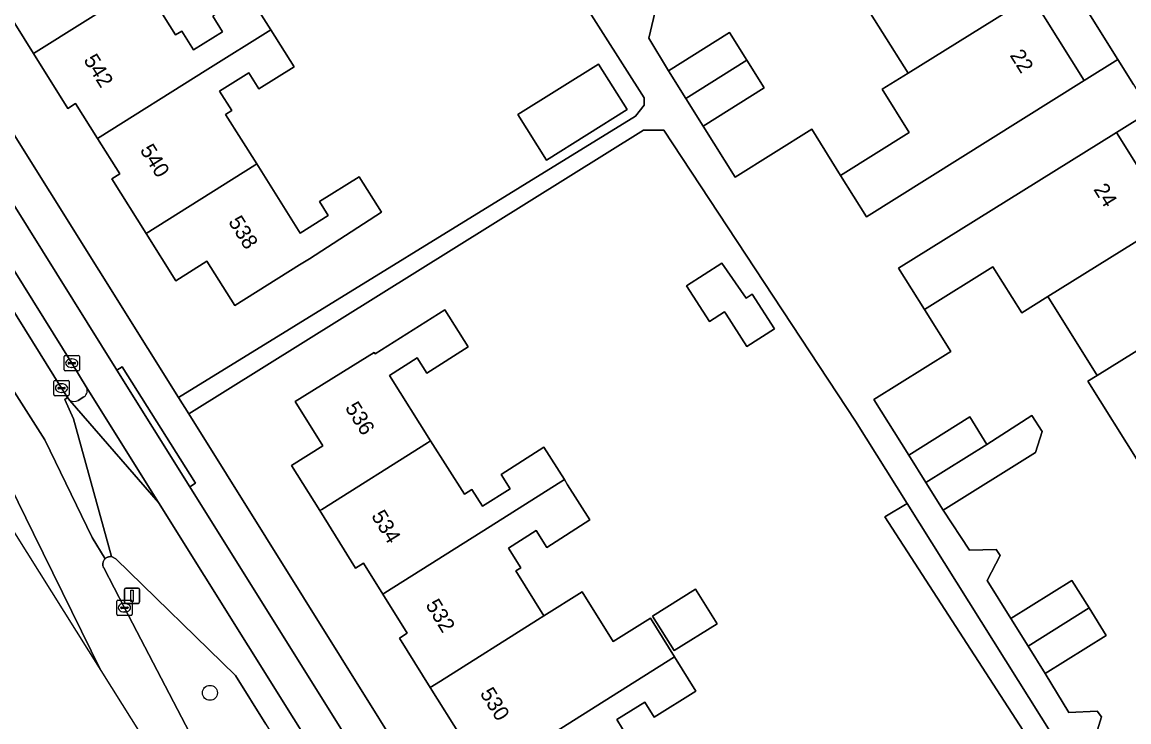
# Model space of a CAD drawing. Extents: x 159664 to 160323, y 385312 to 386115.
# Drawn here: x 159717.3 to 159789.6, y 385791.8 to 385837.6 of the extents above; entities that cross this region are included whole.
import ezdxf

# ---------------------------------------------------------------- set-up
doc = ezdxf.new("R2010")
doc.units = 0
for name, color, linetype in [('IMGEO_Berm_groen', 7, 'Continuous'), ('IMGEO_Berm_open', 7, 'Continuous'), ('IMGEO_Boom', 7, 'Continuous'), ('IMGEO_Erf', 7, 'Continuous'), ('IMGEO_Fietspad_gesloten', 7, 'Continuous'), ('IMGEO_Kolk', 7, 'Continuous'), ('IMGEO_Lichtmast', 7, 'Continuous'), ('IMGEO_Pand', 7, 'Continuous'), ('IMGEO_Pand_nummerreeks', 7, 'Continuous'), ('IMGEO_Rijbaan_lokaal_open', 7, 'Continuous'), ('IMGEO_Rijbaan_regionaal_gesloten', 7, 'Continuous'), ('IMGEO_Verkeerseiland_open', 7, 'Continuous'), ('IMGEO_Voetpad_open', 7, 'Continuous')]:
    doc.layers.add(name, color=color, linetype=linetype)

msp = doc.modelspace()

# ---------------------------------------------------------------- linework, layer by layer
at = {"layer": 'IMGEO_Berm_groen'}
msp.add_lwpolyline([(159733.256, 385791.672), (159731.268, 385794.861), (159723.446, 385802.492), (159723.154, 385802.631), (159723.109, 385802.634), (159723.064, 385802.633), (159723.019, 385802.628), (159722.975, 385802.619), (159722.932, 385802.607), (159722.891, 385802.59), (159722.85, 385802.57), (159722.812, 385802.546), (159722.776, 385802.519), (159722.743, 385802.489), (159722.712, 385802.456), (159722.685, 385802.42), (159722.661, 385802.382), (159722.64, 385802.342), (159722.623, 385802.301), (159722.61, 385802.258), (159722.601, 385802.214), (159722.595, 385802.169), (159722.594, 385802.124), (159722.596, 385802.079), (159722.603, 385802.035), (159722.614, 385801.991), (159722.628, 385801.949), (159722.646, 385801.907), (159722.655, 385801.891), (159724.007, 385799.293), (159732.539, 385782.948)], dxfattribs=at)
at = {"layer": 'IMGEO_Berm_open'}
for points in [[(159685.962, 385868.059), (159687.762, 385865.202), (159698.166, 385848.523), (159707.398, 385833.746), (159719.9, 385813.65), (159720.286, 385813.027), (159720.44, 385812.85)], [(159721.514, 385813.73), (159720.566, 385815.282), (159708.631, 385834.436), (159699.356, 385849.333)], [(159720.974, 385812.847), (159721.354, 385813.072)]]:
    msp.add_lwpolyline(points, dxfattribs=at)
for centre, radius, start, end in [((159721.093, 385813.484), 0.487, 302.33394, 30.33234), ((159720.709, 385813.245), 0.478, 235.73011, 303.62613)]:
    msp.add_arc(centre, radius, start, end, dxfattribs=at)
at = {"layer": 'IMGEO_Boom'}
msp.add_circle((159729.595, 385793.73), 0.489, dxfattribs=at)
at = {"layer": 'IMGEO_Erf'}
for points in [[(159783.276, 385839.278), (159786.733, 385833.76), (159788.93, 385835.134), (159751.956, 385894.264)], [(159725.268, 385840.05), (159727.349, 385836.736), (159727.751, 385836.987), (159728.525, 385835.755), (159730.423, 385836.946), (159729.78, 385837.969)], [(159732.097, 385839.423), (159733.573, 385837.072), (159735.091, 385834.653), (159732.786, 385833.206), (159732.126, 385834.258), (159730.218, 385833.06), (159731.015, 385831.789), (159730.621, 385831.542), (159732.653, 385828.305), (159735.492, 385823.783), (159737.318, 385824.93), (159736.747, 385825.839), (159739.344, 385827.469), (159740.804, 385825.144), (159736.096, 385822.103), (159735.453, 385821.701), (159731.213, 385819.05), (159729.401, 385821.949), (159727.359, 385820.673), (159725.422, 385823.767), (159723.188, 385827.336), (159723.697, 385827.654), (159722.25, 385829.965), (159720.818, 385832.253), (159720.309, 385831.935), (159718.061, 385835.526), (159716.118, 385838.631)], [(159758.773, 385838.63), (159758.279, 385836.531), (159759.569, 385834.393), (159763.553, 385836.886), (159764.684, 385835.078), (159765.816, 385833.27), (159761.832, 385830.777), (159763.92, 385827.44), (159768.92, 385830.568), (159770.808, 385827.55), (159775.293, 385830.356), (159773.526, 385833.182), (159775.221, 385834.242), (159771.881, 385839.579)], [(159791.049, 385831.741), (159788.849, 385830.368), (159792.419, 385824.644)], [(159790.298, 385808.779), (159786.975, 385814.104), (159787.57, 385814.477), (159784.343, 385819.629), (159782.647, 385818.568), (159780.758, 385821.586), (159776.283, 385818.784), (159778.004, 385816.035), (159772.991, 385812.903), (159775.26, 385809.272), (159779.246, 385811.762), (159780.372, 385809.96), (159783.313, 385811.855), (159783.99, 385810.805), (159783.539, 385809.433), (159777.512, 385805.668), (159779.229, 385803.051), (159780.975, 385803.096), (159781.246, 385802.718), (159780.378, 385801.07), (159781.934, 385798.585), (159785.917, 385801.08), (159787.044, 385799.281), (159788.171, 385797.481), (159784.188, 385794.986), (159785.732, 385792.454), (159787.572, 385792.541), (159787.852, 385792.159), (159787.239, 385790.114)], [(159746.012, 385790.854), (159743.996, 385794.079), (159741.978, 385797.309), (159742.487, 385797.628), (159740.892, 385800.18), (159739.625, 385802.208), (159739.116, 385801.889), (159736.772, 385805.64), (159734.93, 385808.589), (159736.982, 385809.871), (159735.174, 385812.764), (159739.415, 385815.414), (159740.333, 385815.987), (159740.399, 385815.883), (159744.948, 385818.761), (159746.479, 385816.339), (159743.771, 385814.626), (159743.141, 385815.622), (159741.32, 385814.47), (159744.016, 385810.208), (159746.224, 385806.717), (159746.719, 385807.03), (159747.417, 385805.928), (159749.213, 385807.064), (159748.617, 385808.006), (159751.424, 385809.782), (159752.763, 385807.665), (159752.973, 385807.333), (159754.43, 385805.029), (159751.603, 385803.24), (159750.908, 385804.338), (159749.1, 385803.195), (159749.913, 385801.91), (159749.581, 385801.7), (159751.412, 385798.755), (159753.919, 385800.336), (159755.95, 385797.087), (159758.386, 385798.601), (159759.952, 385796.081), (159761.352, 385793.828), (159758.637, 385792.14), (159758.025, 385793.125), (159756.179, 385791.978), (159756.929, 385790.771)]]:
    msp.add_lwpolyline(points, dxfattribs=at)
for points in [[(159749.78, 385845.505), (159747.52, 385845.517), (159747.246, 385845.967), (159748.353, 385847.97), (159740.221, 385860.856), (159709.605, 385841.691), (159725.533, 385816.246), (159727.547, 385813.028), (159757.404, 385831.429), (159757.978, 385832.141), (159757.978, 385832.633)], [(159749.726, 385831.528), (159754.992, 385834.824), (159756.851, 385831.852), (159751.585, 385828.557)], [(159775.161, 385806.096), (159771.78, 385811.483), (159759.25, 385830.512), (159757.926, 385830.512), (159728.212, 385811.963), (159753.159, 385772), (159771.727, 385783.591), (159776.451, 385786.658), (159782.979, 385790.896), (159773.707, 385805.242)], [(159760.745, 385820.332), (159763.053, 385821.817), (159764.632, 385819.537), (159765.029, 385819.793), (159766.49, 385817.524), (159764.693, 385816.367), (159763.336, 385818.476), (159763.233, 385818.637), (159762.245, 385818.001)], [(159758.528, 385798.751), (159761.338, 385800.498), (159762.738, 385798.245), (159759.928, 385796.498)]]:
    msp.add_lwpolyline(points, close=True, dxfattribs=at)
at = {"layer": 'IMGEO_Fietspad_gesloten'}
msp.add_lwpolyline([(159689.016, 385865.92), (159699.356, 385849.333), (159708.631, 385834.436), (159720.566, 385815.282), (159721.514, 385813.73), (159726.241, 385806.163), (159746.799, 385773.289), (159761.349, 385750), (159769.568, 385736.844), (159790.48, 385703.378), (159792.384, 385704.563), (159772.652, 385736.21), (159767.476, 385744.488), (159764.031, 385750), (159753.712, 385766.513), (159748.937, 385774.15), (159728.287, 385807.194), (159723.506, 385814.826), (159723.438, 385814.935), (159698.624, 385854.738), (159688.899, 385870.747), (159686.756, 385869.506), (159687.159, 385868.865)], close=True, dxfattribs=at)
at = {"layer": 'IMGEO_Kolk'}
for p, q in [((159720.065, 385814.854), (159720.065, 385815.706)), ((159720.14, 385815.78), (159720.992, 385815.78)), ((159720.324, 385815.274), (159720.324, 385815.286)), ((159720.762, 385815.237), (159720.364, 385815.237)), ((159720.367, 385815.323), (159720.765, 385815.323)), ((159720.553, 385815.56), (159720.578, 385815.56)), ((159720.808, 385815.286), (159720.808, 385815.274)), ((159721.066, 385815.706), (159721.066, 385814.854)), ((159720.992, 385814.78), (159720.14, 385814.78)), ((159720.576, 385815), (159720.551, 385815)), ((159719.398, 385813.223), (159719.398, 385814.075)), ((159719.473, 385814.149), (159720.325, 385814.149)), ((159719.886, 385813.929), (159719.911, 385813.929)), ((159720.399, 385814.075), (159720.399, 385813.223)), ((159720.325, 385813.149), (159719.473, 385813.149)), ((159719.657, 385813.643), (159719.657, 385813.655)), ((159720.095, 385813.606), (159719.697, 385813.606)), ((159719.7, 385813.692), (159720.098, 385813.692)), ((159719.909, 385813.369), (159719.884, 385813.369)), ((159720.141, 385813.655), (159720.141, 385813.643)), ((159723.507, 385798.868), (159723.507, 385799.72)), ((159723.582, 385799.794), (159724.434, 385799.794)), ((159723.766, 385799.288), (159723.766, 385799.3)), ((159723.809, 385799.337), (159724.207, 385799.337)), ((159723.995, 385799.574), (159724.02, 385799.574)), ((159724.25, 385799.3), (159724.25, 385799.288)), ((159724.508, 385799.72), (159724.508, 385798.868)), ((159724.434, 385798.794), (159723.582, 385798.794)), ((159724.204, 385799.251), (159723.806, 385799.251)), ((159724.018, 385799.014), (159723.993, 385799.014))]:
    msp.add_line(p, q, dxfattribs=at)
for points in [[(159720.065, 385814.854), (159720.065, 385815.706)], [(159720.14, 385815.78), (159720.992, 385815.78)], [(159721.066, 385815.706), (159721.066, 385814.854)], [(159720.992, 385814.78), (159720.14, 385814.78)], [(159719.398, 385813.223), (159719.398, 385814.075)], [(159719.473, 385814.149), (159720.325, 385814.149)], [(159720.399, 385814.075), (159720.399, 385813.223)], [(159720.325, 385813.149), (159719.473, 385813.149)], [(159723.507, 385798.868), (159723.507, 385799.72)], [(159723.582, 385799.794), (159724.434, 385799.794)], [(159724.508, 385799.72), (159724.508, 385798.868)], [(159724.434, 385798.794), (159723.582, 385798.794)]]:
    msp.add_lwpolyline(points, dxfattribs=at)
for centre, radius, start, end in [((159720.142, 385815.704), 0.0765, 91.55205, 178.44795), ((159720.142, 385815.704), 0.0765, 91.55205, 178.44795), ((159720.364, 385815.283), 0.0403, 85.87752, 175.75265), ((159720.361, 385815.273), 0.0366, 178.93798, 274.71019), ((159720.765, 385815.28), 0.043, 264.86636, 352.45326), ((159720.769, 385815.285), 0.0386, 1.73085, 96.63898), ((159720.99, 385815.704), 0.0765, 1.55205, 88.44795), ((159720.99, 385815.704), 0.0765, 1.55205, 88.44795), ((159720.142, 385814.856), 0.0765, 181.55205, 268.44795), ((159720.142, 385814.856), 0.0765, 181.55205, 268.44795), ((159720.99, 385814.856), 0.0765, 271.55205, 358.44795), ((159720.99, 385814.856), 0.0765, 271.55205, 358.44795), ((159719.475, 385814.073), 0.0765, 91.55205, 178.44795), ((159719.475, 385814.073), 0.0765, 91.55205, 178.44795), ((159720.323, 385814.073), 0.0765, 1.55205, 88.44795), ((159720.323, 385814.073), 0.0765, 1.55205, 88.44795), ((159719.475, 385813.225), 0.0765, 181.55205, 268.44795), ((159719.475, 385813.225), 0.0765, 181.55205, 268.44795), ((159719.697, 385813.652), 0.0403, 85.87752, 175.75265), ((159719.694, 385813.642), 0.0366, 178.93798, 274.71019), ((159720.098, 385813.649), 0.043, 264.86636, 352.45326), ((159720.102, 385813.654), 0.0386, 1.73085, 96.63898), ((159720.323, 385813.225), 0.0765, 271.55205, 358.44795), ((159720.323, 385813.225), 0.0765, 271.55205, 358.44795), ((159723.584, 385799.718), 0.0765, 91.55205, 178.44795), ((159723.584, 385799.718), 0.0765, 91.55205, 178.44795), ((159723.806, 385799.297), 0.0403, 85.87752, 175.75265), ((159723.803, 385799.287), 0.0366, 178.93798, 274.71019), ((159724.207, 385799.294), 0.043, 264.86636, 352.45326), ((159724.211, 385799.299), 0.0386, 1.73085, 96.63898), ((159724.432, 385799.718), 0.0765, 1.55205, 88.44795), ((159724.432, 385799.718), 0.0765, 1.55205, 88.44795), ((159723.584, 385798.87), 0.0765, 181.55205, 268.44795), ((159723.584, 385798.87), 0.0765, 181.55205, 268.44795), ((159724.432, 385798.87), 0.0765, 271.55205, 358.44795), ((159724.432, 385798.87), 0.0765, 271.55205, 358.44795)]:
    msp.add_arc(centre, radius, start, end, dxfattribs=at)
for centre, major_axis, ratio, start_param, end_param in [((159720.552, 385815.28), (-0.387, 0.002), 0.722429, 4.712389, 7.853982), ((159720.577, 385815.28), (-0.39, 0.002), 0.717154, 1.570796, 4.712389), ((159719.885, 385813.649), (-0.387, 0.002), 0.722429, 4.712389, 7.853982), ((159719.91, 385813.649), (-0.39, 0.002), 0.717154, 1.570796, 4.712389), ((159723.994, 385799.294), (-0.387, 0.002), 0.722429, 4.712389, 7.853982), ((159724.019, 385799.294), (-0.39, 0.002), 0.717154, 1.570796, 4.712389)]:
    msp.add_ellipse(centre, major_axis=major_axis, ratio=ratio, start_param=start_param, end_param=end_param, dxfattribs=at)
at = {"layer": 'IMGEO_Lichtmast'}
for p, q in [((159724.005, 385799.674), (159724.005, 385800.474)), ((159724.005, 385800.474), (159724.005, 385799.674)), ((159724.105, 385800.574), (159724.895, 385800.574)), ((159724.895, 385800.574), (159724.105, 385800.574)), ((159724.995, 385800.474), (159724.995, 385799.674)), ((159724.995, 385799.674), (159724.995, 385800.474)), ((159724.895, 385799.574), (159724.105, 385799.574)), ((159724.105, 385799.574), (159724.895, 385799.574))]:
    msp.add_line(p, q, dxfattribs=at)
msp.add_lwpolyline([(159724.425, 385800.449), (159724.575, 385800.449), (159724.575, 385799.699), (159724.425, 385799.699), (159724.425, 385800.449)], dxfattribs=at)
for centre, start, end in [((159724.105, 385800.474), 90, 180), ((159724.105, 385800.474), 90, 180), ((159724.895, 385800.474), 0, 90), ((159724.895, 385800.474), 360, 90), ((159724.105, 385799.674), 180, 270), ((159724.105, 385799.674), 180, 270), ((159724.895, 385799.674), 270, 0), ((159724.895, 385799.674), 270, 0)]:
    msp.add_arc(centre, 0.1, start, end, dxfattribs=at)
at = {"layer": 'IMGEO_Pand'}
for points in [[(159716.363, 385842.815), (159718.175, 385839.916), (159716.118, 385838.631), (159718.061, 385835.526), (159725.165, 385839.985), (159725.268, 385840.05), (159722.462, 385844.52), (159724.34, 385845.699), (159724.924, 385844.769), (159724.715, 385844.637), (159725.712, 385843.049), (159728.503, 385844.802), (159726.034, 385848.734), (159721.394, 385845.894)], [(159780.04, 385844.443), (159779.933, 385844.614), (159771.881, 385839.579), (159775.221, 385834.242), (159783.276, 385839.278)], [(159725.165, 385839.985), (159718.061, 385835.526), (159720.309, 385831.935), (159720.818, 385832.253), (159722.25, 385829.965), (159729.463, 385834.492), (159733.573, 385837.072), (159732.097, 385839.423), (159729.78, 385837.969), (159730.423, 385836.946), (159728.525, 385835.755), (159727.751, 385836.987), (159727.349, 385836.736), (159725.268, 385840.05)], [(159786.733, 385833.76), (159783.276, 385839.278), (159775.221, 385834.242), (159773.526, 385833.182), (159775.293, 385830.356), (159770.808, 385827.55), (159772.494, 385824.856)], [(159729.463, 385834.492), (159722.25, 385829.965), (159723.697, 385827.654), (159723.188, 385827.336), (159725.422, 385823.767), (159732.519, 385828.221), (159732.653, 385828.305), (159730.621, 385831.542), (159731.015, 385831.789), (159730.218, 385833.06), (159732.126, 385834.258), (159732.786, 385833.206), (159735.091, 385834.653), (159733.573, 385837.072)], [(159763.553, 385836.886), (159759.569, 385834.393), (159760.7, 385832.585), (159764.684, 385835.078)], [(159749.726, 385831.528), (159751.585, 385828.557), (159756.851, 385831.852), (159754.992, 385834.824)], [(159765.816, 385833.27), (159764.684, 385835.078), (159760.7, 385832.585), (159761.832, 385830.777)], [(159784.343, 385819.629), (159792.419, 385824.644), (159788.849, 385830.368), (159774.595, 385821.481), (159776.283, 385818.784), (159780.758, 385821.586), (159782.647, 385818.568)], [(159732.519, 385828.221), (159725.422, 385823.767), (159727.359, 385820.673), (159729.401, 385821.949), (159731.213, 385819.05), (159735.453, 385821.701), (159736.096, 385822.103), (159740.804, 385825.144), (159739.344, 385827.469), (159736.747, 385825.839), (159737.318, 385824.93), (159735.492, 385823.783), (159732.653, 385828.305)], [(159795.515, 385819.679), (159792.419, 385824.644), (159784.343, 385819.629), (159787.57, 385814.477), (159795.636, 385819.485)], [(159763.053, 385821.817), (159760.745, 385820.332), (159762.245, 385818.001), (159763.233, 385818.637), (159763.336, 385818.476), (159764.693, 385816.367), (159766.49, 385817.524), (159765.029, 385819.793), (159764.632, 385819.537)], [(159796.231, 385819.855), (159796.109, 385820.05), (159795.515, 385819.679), (159795.636, 385819.485), (159787.57, 385814.477), (159786.975, 385814.104), (159790.298, 385808.779), (159798.37, 385813.791), (159798.487, 385813.604), (159799.675, 385814.346), (159799.56, 385814.53)], [(159744.016, 385810.208), (159741.32, 385814.47), (159743.141, 385815.622), (159743.771, 385814.626), (159746.479, 385816.339), (159744.948, 385818.761), (159740.399, 385815.883), (159740.333, 385815.987), (159739.415, 385815.414), (159735.174, 385812.764), (159736.982, 385809.871), (159734.93, 385808.589), (159736.772, 385805.64), (159736.902, 385805.722), (159743.802, 385810.073)], [(159779.246, 385811.762), (159775.26, 385809.272), (159776.386, 385807.47), (159780.372, 385809.96)], [(159783.313, 385811.855), (159780.372, 385809.96), (159776.386, 385807.47), (159777.512, 385805.668), (159783.539, 385809.433), (159783.99, 385810.805)], [(159746.719, 385807.03), (159746.224, 385806.717), (159744.016, 385810.208), (159743.802, 385810.073), (159736.902, 385805.722), (159736.772, 385805.64), (159739.116, 385801.889), (159739.625, 385802.208), (159740.892, 385800.18), (159741.018, 385800.259), (159747.909, 385804.605), (159752.763, 385807.665), (159751.424, 385809.782), (159748.617, 385808.006), (159749.213, 385807.064), (159747.417, 385805.928)], [(159749.1, 385803.195), (159750.908, 385804.338), (159751.603, 385803.24), (159754.43, 385805.029), (159752.973, 385807.333), (159752.763, 385807.665), (159747.909, 385804.605), (159741.018, 385800.259), (159740.892, 385800.18), (159742.487, 385797.628), (159741.978, 385797.309), (159743.996, 385794.079), (159744.653, 385794.493), (159750.997, 385798.493), (159751.412, 385798.755), (159749.581, 385801.7), (159749.913, 385801.91)], [(159787.044, 385799.281), (159785.917, 385801.08), (159781.934, 385798.585), (159783.061, 385796.785)], [(159759.952, 385796.081), (159758.386, 385798.601), (159755.95, 385797.087), (159753.919, 385800.336), (159751.412, 385798.755), (159750.997, 385798.493), (159744.653, 385794.493), (159743.996, 385794.079), (159746.012, 385790.854), (159746.522, 385791.172), (159748.117, 385788.619), (159748.289, 385788.727), (159755.36, 385793.186)], [(159758.528, 385798.751), (159759.928, 385796.498), (159762.738, 385798.245), (159761.338, 385800.498)], [(159783.061, 385796.785), (159784.188, 385794.986), (159788.171, 385797.481), (159787.044, 385799.281)], [(159758.584, 385787.162), (159756.505, 385790.508), (159756.929, 385790.771), (159756.179, 385791.978), (159758.025, 385793.125), (159758.637, 385792.14), (159761.352, 385793.828), (159759.952, 385796.081), (159755.36, 385793.186), (159748.289, 385788.727), (159748.117, 385788.619), (159749.399, 385786.567), (159748.89, 385786.249), (159751.221, 385782.519), (159751.393, 385782.627), (159758.36, 385787.02)]]:
    msp.add_lwpolyline(points, close=True, dxfattribs=at)
at = {"layer": 'IMGEO_Rijbaan_lokaal_open'}
msp.add_lwpolyline([(159720.286, 385813.027), (159720.121, 385812.906), (159720.687, 385811.648), (159723.154, 385802.631), (159723.446, 385802.492), (159731.268, 385794.861), (159733.256, 385791.672), (159735.48, 385788.106), (159745.908, 385771.421), (159759.303, 385750), (159767.282, 385737.246), (159778.388, 385719.445), (159788.935, 385702.551), (159789.008, 385702.435), (159790.48, 385703.378), (159769.568, 385736.844), (159761.349, 385750), (159746.799, 385773.289), (159726.241, 385806.163), (159720.44, 385812.85)], close=True, dxfattribs=at)
at = {"layer": 'IMGEO_Rijbaan_regionaal_gesloten'}
for points in [[(159707.398, 385833.746), (159698.166, 385848.523), (159687.762, 385865.202), (159685.962, 385868.059), (159683.457, 385865.842), (159689.98, 385855.614), (159704.448, 385832.81), (159718.81, 385810.264), (159721.888, 385803.885), (159722.743, 385802.489), (159722.776, 385802.519), (159722.812, 385802.546), (159722.85, 385802.57), (159722.891, 385802.59), (159722.932, 385802.607), (159722.975, 385802.619), (159723.019, 385802.628), (159723.064, 385802.633), (159723.109, 385802.634), (159723.154, 385802.631), (159720.687, 385811.648), (159720.121, 385812.906), (159720.286, 385813.027), (159719.9, 385813.65)], [(159722.474, 385795.185), (159718.071, 385804.138), (159716.049, 385808.25), (159711.375, 385815.569), (159700.472, 385832.883), (159681.056, 385863.717), (159680.046, 385862.823)]]:
    msp.add_lwpolyline(points, close=True, dxfattribs=at)
for points in [[(159681.056, 385863.717), (159700.472, 385832.883), (159711.375, 385815.569), (159716.049, 385808.25), (159718.071, 385804.138), (159722.474, 385795.185), (159793.146, 385682.519)], [(159732.539, 385782.948), (159724.007, 385799.293), (159722.655, 385801.891), (159722.646, 385801.907), (159722.628, 385801.949), (159722.614, 385801.991), (159722.603, 385802.035), (159722.596, 385802.079), (159722.594, 385802.124), (159722.595, 385802.169), (159722.601, 385802.214), (159722.61, 385802.258), (159722.623, 385802.301), (159722.64, 385802.342), (159722.661, 385802.382), (159722.685, 385802.42), (159722.712, 385802.456), (159722.743, 385802.489), (159721.888, 385803.885), (159718.81, 385810.264), (159704.448, 385832.81)]]:
    msp.add_lwpolyline(points, dxfattribs=at)
at = {"layer": 'IMGEO_Verkeerseiland_open'}
for points in [[(159720.44, 385812.85), (159726.241, 385806.163), (159721.514, 385813.73)], [(159721.354, 385813.072), (159720.974, 385812.847)]]:
    msp.add_lwpolyline(points, dxfattribs=at)
for centre, radius, start, end in [((159721.093, 385813.484), 0.487, 302.33394, 30.33234), ((159720.709, 385813.245), 0.478, 235.73011, 303.62613)]:
    msp.add_arc(centre, radius, start, end, dxfattribs=at)
at = {"layer": 'IMGEO_Voetpad_open'}
for points in [[(159741.032, 385918.933), (159740.787, 385919.315), (159737.177, 385917.789), (159749.768, 385897.575), (159749.851, 385897.63), (159751.956, 385894.264), (159788.93, 385835.134), (159789.958, 385833.49), (159791.049, 385831.741), (159827.962, 385772.584), (159830.13, 385769.11), (159843.706, 385747.354)], [(159698.624, 385854.738), (159723.438, 385814.935), (159723.506, 385814.826), (159723.865, 385815.051), (159728.647, 385807.43), (159728.287, 385807.194), (159748.937, 385774.15), (159749.31, 385774.375), (159754.077, 385766.751), (159753.712, 385766.513), (159764.031, 385750)], [(159749.78, 385845.505), (159757.978, 385832.633), (159757.978, 385832.141), (159757.404, 385831.429), (159727.547, 385813.028), (159728.212, 385811.963), (159757.926, 385830.512), (159759.25, 385830.512), (159771.78, 385811.483), (159775.161, 385806.096), (159790.372, 385781.858)], [(159728.212, 385811.963), (159727.547, 385813.028), (159725.533, 385816.246), (159709.605, 385841.691)], [(159789.958, 385833.49), (159788.93, 385835.134), (159786.733, 385833.76), (159772.494, 385824.856), (159770.808, 385827.55), (159768.92, 385830.568), (159763.92, 385827.44), (159761.832, 385830.777), (159760.7, 385832.585), (159759.569, 385834.393), (159758.279, 385836.531), (159758.773, 385838.63)], [(159789.739, 385786.105), (159788.616, 385787.906), (159787.239, 385790.114), (159787.852, 385792.159), (159787.572, 385792.541), (159785.732, 385792.454), (159784.188, 385794.986), (159783.061, 385796.785), (159781.934, 385798.585), (159780.378, 385801.07), (159781.246, 385802.718), (159780.975, 385803.096), (159779.229, 385803.051), (159777.512, 385805.668), (159776.386, 385807.47), (159775.26, 385809.272), (159772.991, 385812.903), (159778.004, 385816.035), (159776.283, 385818.784), (159774.595, 385821.481), (159788.849, 385830.368), (159791.049, 385831.741)], [(159766.915, 385750), (159753.983, 385770.681), (159753.16, 385771.998), (159753.159, 385772), (159728.212, 385811.963)]]:
    msp.add_lwpolyline(points, dxfattribs=at)
for points in [[(159723.506, 385814.826), (159728.287, 385807.194), (159728.647, 385807.43), (159723.865, 385815.051)], [(159775.161, 385806.096), (159773.707, 385805.242), (159782.979, 385790.896), (159776.451, 385786.658), (159771.727, 385783.591), (159753.159, 385772), (159753.16, 385771.998), (159753.983, 385770.681), (159778.24, 385785.96), (159783.787, 385789.454), (159789.083, 385781.046), (159790.372, 385781.858)]]:
    msp.add_lwpolyline(points, close=True, dxfattribs=at)

# ---------------------------------------------------------------- texts
at = {"layer": 'IMGEO_Pand_nummerreeks'}
for s, rotation, p in [('542', 302.04527, (159721.305, 385835.095)), ('22', 302.01094, (159781.837, 385835.407)), ('540', 302.04527, (159724.988, 385829.21)), ('24', 301.98947, (159787.31, 385826.643)), ('538', 301.99996, (159730.765, 385824.522)), ('536', 301.99473, (159738.394, 385812.367)), ('534', 301.35777, (159740.11, 385805.298)), ('532', 301.35777, (159743.656, 385799.48)), ('530', 302.00521, (159747.21, 385793.691))]:
    msp.add_text(s, height=1, rotation=rotation, dxfattribs=at).set_placement(p)

doc.saveas('drawing.dxf')
